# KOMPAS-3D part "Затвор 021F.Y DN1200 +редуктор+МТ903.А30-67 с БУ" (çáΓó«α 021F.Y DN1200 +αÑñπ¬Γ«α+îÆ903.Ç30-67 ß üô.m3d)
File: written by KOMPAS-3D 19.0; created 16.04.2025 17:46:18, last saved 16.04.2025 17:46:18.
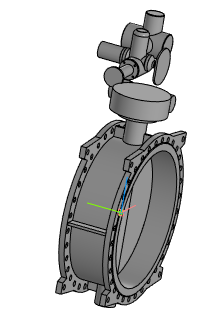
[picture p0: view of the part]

Document properties: Полное имя файла: Затвор 021F.Y DN1200 +редуктор+МТ903.А30-67 с БУ.a3d

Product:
- Part/product: Затвор 021F.Y DN1200 +редуктор+МТ903.А30-67 с БУ
    Масса: 1879.85

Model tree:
1. Операция без истории:1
